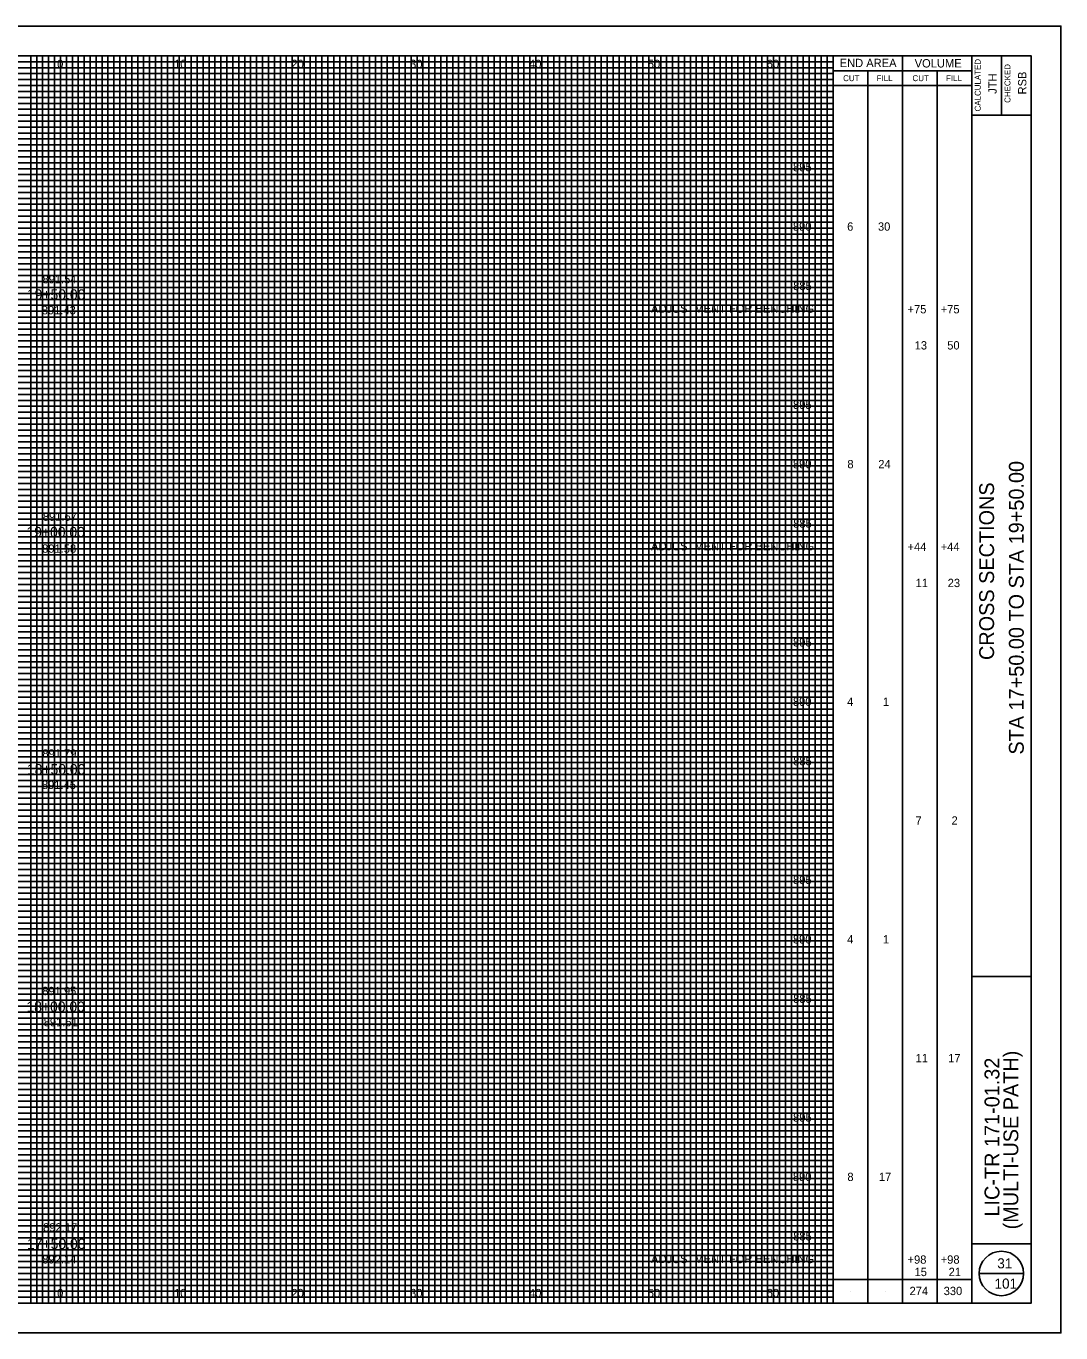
# Model space of a CAD drawing. Extents: x -10 to 160, y -2 to 2522.
# Drawn here: x 72.9 to 160, y 342.5 to 452.5 of the extents above; entities that cross this region are included whole.
import ezdxf

# ---------------------------------------------------------------- set-up
doc = ezdxf.new("R2010")
doc.units = 0
for name, color, linetype in [('GK_Cells', 7, 'Continuous'), ('GK_Patterns', 7, 'Continuous'), ('TX_P_10', 7, 'Continuous'), ('TX_X_10', 7, 'Continuous'), ('XS_P_Finished_Grade_Seeded', 7, 'Continuous'), ('XS_P_Pavt_Surface', 7, 'Continuous'), ('XS_P_Subgrade', 7, 'Continuous'), ('XS_X_Ground_Line', 7, 'Continuous')]:
    doc.layers.add(name, color=color, linetype=linetype)

msp = doc.modelspace()

# ---------------------------------------------------------------- linework, layer by layer
at = {"layer": 'GK_Cells'}
msp.add_lwpolyline([(-10, 342.5), (160, 342.5), (160, 452.5), (-10, 452.5)], close=True, dxfattribs=at)
at = {"layer": 'TX_P_10'}
for p, q in [((140.83, 345), (140.83, 450)), ((146.67, 345), (146.67, 450)), ((140.83, 448.75), (152.5, 448.75)), ((143.75, 345), (143.75, 448.75)), ((149.58, 345), (149.58, 448.75)), ((140.83, 447.5), (152.5, 447.5)), ((140.83, 347), (152.5, 347)), ((153.12, 347.5), (156.88, 347.5)), ((142.29, 346), (142.29, 346)), ((145.21, 346), (145.21, 346)), ((148.12, 346), (148.12, 346)), ((151.04, 346), (151.04, 346))]:
    msp.add_line(p, q, dxfattribs=at)
msp.add_circle((155, 347.5), 1.87, dxfattribs=at)
at = {"layer": 'TX_X_10'}
for p, q in [((75.83, 345), (75.83, 450)), ((80.83, 345), (80.83, 450)), ((85.83, 345), (85.83, 450)), ((90.83, 345), (90.83, 450)), ((95.83, 345), (95.83, 450)), ((100.83, 345), (100.83, 450)), ((105.83, 345), (105.83, 450)), ((110.83, 345), (110.83, 450)), ((115.83, 345), (115.83, 450)), ((120.83, 345), (120.83, 450)), ((125.83, 345), (125.83, 450)), ((130.83, 345), (130.83, 450)), ((135.83, 345), (135.83, 450)), ((5.83, 445), (140.83, 445)), ((5.83, 440), (140.83, 440)), ((5.83, 435), (140.83, 435)), ((5.83, 430), (140.83, 430)), ((5.83, 425), (140.83, 425)), ((5.83, 420), (140.83, 420)), ((5.83, 415), (140.83, 415)), ((5.83, 410), (140.83, 410)), ((5.83, 405), (140.83, 405)), ((5.83, 400), (140.83, 400)), ((5.83, 395), (140.83, 395)), ((5.83, 390), (140.83, 390)), ((5.83, 385), (140.83, 385)), ((5.83, 380), (140.83, 380)), ((5.83, 375), (140.83, 375)), ((5.83, 370), (140.83, 370)), ((5.83, 365), (140.83, 365)), ((5.83, 360), (140.83, 360)), ((5.83, 355), (140.83, 355)), ((5.83, 350), (140.83, 350))]:
    msp.add_line(p, q, dxfattribs=at)
at = {"layer": 'XS_P_Pavt_Surface'}
for p, q in [((152.5, 345), (152.5, 450)), ((155, 450), (155, 445)), ((152.5, 445), (157.5, 445)), ((152.5, 372.5), (157.5, 372.5)), ((152.5, 350), (157.5, 350))]:
    msp.add_line(p, q, dxfattribs=at)
msp.add_lwpolyline([(0, 450), (157.5, 450), (157.5, 345), (0, 345)], close=True, dxfattribs=at)
at = {"layer": 'XS_X_Ground_Line'}
for p, q in [((73.33, 345), (73.33, 450)), ((73.83, 345), (73.83, 450)), ((74.33, 345), (74.33, 450)), ((74.83, 345), (74.83, 450)), ((75.33, 345), (75.33, 450)), ((76.33, 345), (76.33, 450)), ((76.83, 345), (76.83, 450)), ((77.33, 345), (77.33, 450)), ((77.83, 345), (77.83, 450)), ((78.33, 345), (78.33, 450)), ((78.83, 345), (78.83, 450)), ((79.33, 345), (79.33, 450)), ((79.83, 345), (79.83, 450)), ((80.33, 345), (80.33, 450)), ((81.33, 345), (81.33, 450)), ((81.83, 345), (81.83, 450)), ((82.33, 345), (82.33, 450)), ((82.83, 345), (82.83, 450)), ((83.33, 345), (83.33, 450)), ((83.83, 345), (83.83, 450)), ((84.33, 345), (84.33, 450)), ((84.83, 345), (84.83, 450)), ((85.33, 345), (85.33, 450)), ((86.33, 345), (86.33, 450)), ((86.83, 345), (86.83, 450)), ((87.33, 345), (87.33, 450)), ((87.83, 345), (87.83, 450)), ((88.33, 345), (88.33, 450)), ((88.83, 345), (88.83, 450)), ((89.33, 345), (89.33, 450)), ((89.83, 345), (89.83, 450)), ((90.33, 345), (90.33, 450)), ((91.33, 345), (91.33, 450)), ((91.83, 345), (91.83, 450)), ((92.33, 345), (92.33, 450)), ((92.83, 345), (92.83, 450)), ((93.33, 345), (93.33, 450)), ((93.83, 345), (93.83, 450)), ((94.33, 345), (94.33, 450)), ((94.83, 345), (94.83, 450)), ((95.33, 345), (95.33, 450)), ((96.33, 345), (96.33, 450)), ((96.83, 345), (96.83, 450)), ((97.33, 345), (97.33, 450)), ((97.83, 345), (97.83, 450)), ((98.33, 345), (98.33, 450)), ((98.83, 345), (98.83, 450)), ((99.33, 345), (99.33, 450)), ((99.83, 345), (99.83, 450)), ((100.33, 345), (100.33, 450)), ((101.33, 345), (101.33, 450)), ((101.83, 345), (101.83, 450)), ((102.33, 345), (102.33, 450)), ((102.83, 345), (102.83, 450)), ((103.33, 345), (103.33, 450)), ((103.83, 345), (103.83, 450)), ((104.33, 345), (104.33, 450)), ((104.83, 345), (104.83, 450)), ((105.33, 345), (105.33, 450)), ((106.33, 345), (106.33, 450)), ((106.83, 345), (106.83, 450)), ((107.33, 345), (107.33, 450)), ((107.83, 345), (107.83, 450)), ((108.33, 345), (108.33, 450)), ((108.83, 345), (108.83, 450)), ((109.33, 345), (109.33, 450)), ((109.83, 345), (109.83, 450)), ((110.33, 345), (110.33, 450)), ((111.33, 345), (111.33, 450)), ((111.83, 345), (111.83, 450)), ((112.33, 345), (112.33, 450)), ((112.83, 345), (112.83, 450)), ((113.33, 345), (113.33, 450)), ((113.83, 345), (113.83, 450)), ((114.33, 345), (114.33, 450)), ((114.83, 345), (114.83, 450)), ((115.33, 345), (115.33, 450)), ((116.33, 345), (116.33, 450)), ((116.83, 345), (116.83, 450)), ((117.33, 345), (117.33, 450)), ((117.83, 345), (117.83, 450)), ((118.33, 345), (118.33, 450)), ((118.83, 345), (118.83, 450)), ((119.33, 345), (119.33, 450)), ((119.83, 345), (119.83, 450)), ((120.33, 345), (120.33, 450)), ((121.33, 345), (121.33, 450)), ((121.83, 345), (121.83, 450)), ((122.33, 345), (122.33, 450)), ((122.83, 345), (122.83, 450)), ((123.33, 345), (123.33, 450)), ((123.83, 345), (123.83, 450)), ((124.33, 345), (124.33, 450)), ((124.83, 345), (124.83, 450)), ((125.33, 345), (125.33, 450)), ((126.33, 345), (126.33, 450)), ((126.83, 345), (126.83, 450)), ((127.33, 345), (127.33, 450)), ((127.83, 345), (127.83, 450)), ((128.33, 345), (128.33, 450)), ((128.83, 345), (128.83, 450)), ((129.33, 345), (129.33, 450)), ((129.83, 345), (129.83, 450)), ((130.33, 345), (130.33, 450)), ((131.33, 345), (131.33, 450)), ((131.83, 345), (131.83, 450)), ((132.33, 345), (132.33, 450)), ((132.83, 345), (132.83, 450)), ((133.33, 345), (133.33, 450)), ((133.83, 345), (133.83, 450)), ((134.33, 345), (134.33, 450)), ((134.83, 345), (134.83, 450)), ((135.33, 345), (135.33, 450)), ((136.33, 345), (136.33, 450)), ((136.83, 345), (136.83, 450)), ((137.33, 345), (137.33, 450)), ((137.83, 345), (137.83, 450)), ((138.33, 345), (138.33, 450)), ((138.83, 345), (138.83, 450)), ((139.33, 345), (139.33, 450)), ((139.83, 345), (139.83, 450)), ((140.33, 345), (140.33, 450)), ((5.83, 449.5), (140.83, 449.5)), ((5.83, 449), (140.83, 449)), ((5.83, 448.5), (140.83, 448.5)), ((5.83, 448), (140.83, 448)), ((5.83, 447.5), (140.83, 447.5)), ((5.83, 447), (140.83, 447)), ((5.83, 446.5), (140.83, 446.5)), ((5.83, 446), (140.83, 446)), ((5.83, 445.5), (140.83, 445.5)), ((5.83, 444.5), (140.83, 444.5)), ((5.83, 444), (140.83, 444)), ((5.83, 443.5), (140.83, 443.5)), ((5.83, 443), (140.83, 443)), ((5.83, 442.5), (140.83, 442.5)), ((5.83, 442), (140.83, 442)), ((5.83, 441.5), (140.83, 441.5)), ((5.83, 441), (140.83, 441)), ((5.83, 440.5), (140.83, 440.5)), ((5.83, 439.5), (140.83, 439.5)), ((5.83, 439), (140.83, 439)), ((5.83, 438.5), (140.83, 438.5)), ((5.83, 438), (140.83, 438)), ((5.83, 437.5), (140.83, 437.5)), ((5.83, 437), (140.83, 437)), ((5.83, 436.5), (140.83, 436.5)), ((5.83, 436), (140.83, 436)), ((5.83, 435.5), (140.83, 435.5)), ((5.83, 434.5), (140.83, 434.5)), ((5.83, 434), (140.83, 434)), ((5.83, 433.5), (140.83, 433.5)), ((5.83, 433), (140.83, 433)), ((5.83, 432.5), (140.83, 432.5)), ((5.83, 432), (140.83, 432)), ((5.83, 431.5), (140.83, 431.5)), ((5.83, 431), (140.83, 431)), ((5.83, 430.5), (140.83, 430.5)), ((5.83, 429.5), (140.83, 429.5)), ((5.83, 429), (140.83, 429)), ((5.83, 428.5), (140.83, 428.5)), ((5.83, 428), (140.83, 428)), ((5.83, 427.5), (140.83, 427.5)), ((5.83, 427), (140.83, 427)), ((5.83, 426.5), (140.83, 426.5)), ((5.83, 426), (140.83, 426)), ((5.83, 425.5), (140.83, 425.5)), ((5.83, 424.5), (140.83, 424.5)), ((5.83, 424), (140.83, 424)), ((5.83, 423.5), (140.83, 423.5)), ((5.83, 423), (140.83, 423)), ((5.83, 422.5), (140.83, 422.5)), ((5.83, 422), (140.83, 422)), ((5.83, 421.5), (140.83, 421.5)), ((5.83, 421), (140.83, 421)), ((5.83, 420.5), (140.83, 420.5)), ((5.83, 419.5), (140.83, 419.5)), ((5.83, 419), (140.83, 419)), ((5.83, 418.5), (140.83, 418.5)), ((5.83, 418), (140.83, 418)), ((5.83, 417.5), (140.83, 417.5)), ((5.83, 417), (140.83, 417)), ((5.83, 416.5), (140.83, 416.5)), ((5.83, 416), (140.83, 416)), ((5.83, 415.5), (140.83, 415.5)), ((5.83, 414.5), (140.83, 414.5)), ((5.83, 414), (140.83, 414)), ((5.83, 413.5), (140.83, 413.5)), ((5.83, 413), (140.83, 413)), ((5.83, 412.5), (140.83, 412.5)), ((5.83, 412), (140.83, 412)), ((5.83, 411.5), (140.83, 411.5)), ((5.83, 411), (140.83, 411)), ((5.83, 410.5), (140.83, 410.5)), ((5.83, 409.5), (140.83, 409.5)), ((5.83, 409), (140.83, 409)), ((5.83, 408.5), (140.83, 408.5)), ((5.83, 408), (140.83, 408)), ((5.83, 407.5), (140.83, 407.5)), ((5.83, 407), (140.83, 407)), ((5.83, 406.5), (140.83, 406.5)), ((5.83, 406), (140.83, 406)), ((5.83, 405.5), (140.83, 405.5)), ((5.83, 404.5), (140.83, 404.5)), ((5.83, 404), (140.83, 404)), ((5.83, 403.5), (140.83, 403.5)), ((5.83, 403), (140.83, 403)), ((5.83, 402.5), (140.83, 402.5)), ((5.83, 402), (140.83, 402)), ((5.83, 401.5), (140.83, 401.5)), ((5.83, 401), (140.83, 401)), ((5.83, 400.5), (140.83, 400.5)), ((5.83, 399.5), (140.83, 399.5)), ((5.83, 399), (140.83, 399)), ((5.83, 398.5), (140.83, 398.5)), ((5.83, 398), (140.83, 398)), ((5.83, 397.5), (140.83, 397.5)), ((5.83, 397), (140.83, 397)), ((5.83, 396.5), (140.83, 396.5)), ((5.83, 396), (140.83, 396)), ((5.83, 395.5), (140.83, 395.5)), ((5.83, 394.5), (140.83, 394.5)), ((5.83, 394), (140.83, 394)), ((5.83, 393.5), (140.83, 393.5)), ((5.83, 393), (140.83, 393)), ((5.83, 392.5), (140.83, 392.5)), ((5.83, 392), (140.83, 392)), ((5.83, 391.5), (140.83, 391.5)), ((5.83, 391), (140.83, 391)), ((5.83, 390.5), (140.83, 390.5)), ((5.83, 389.5), (140.83, 389.5)), ((5.83, 389), (140.83, 389)), ((5.83, 388.5), (140.83, 388.5)), ((5.83, 388), (140.83, 388)), ((5.83, 387.5), (140.83, 387.5)), ((5.83, 387), (140.83, 387)), ((5.83, 386.5), (140.83, 386.5)), ((5.83, 386), (140.83, 386)), ((5.83, 385.5), (140.83, 385.5)), ((5.83, 384.5), (140.83, 384.5)), ((5.83, 384), (140.83, 384)), ((5.83, 383.5), (140.83, 383.5)), ((5.83, 383), (140.83, 383)), ((5.83, 382.5), (140.83, 382.5)), ((5.83, 382), (140.83, 382)), ((5.83, 381.5), (140.83, 381.5)), ((5.83, 381), (140.83, 381)), ((5.83, 380.5), (140.83, 380.5)), ((5.83, 379.5), (140.83, 379.5)), ((5.83, 379), (140.83, 379)), ((5.83, 378.5), (140.83, 378.5)), ((5.83, 378), (140.83, 378)), ((5.83, 377.5), (140.83, 377.5)), ((5.83, 377), (140.83, 377)), ((5.83, 376.5), (140.83, 376.5)), ((5.83, 376), (140.83, 376)), ((5.83, 375.5), (140.83, 375.5)), ((5.83, 374.5), (140.83, 374.5)), ((5.83, 374), (140.83, 374)), ((5.83, 373.5), (140.83, 373.5)), ((5.83, 373), (140.83, 373)), ((5.83, 372.5), (140.83, 372.5)), ((5.83, 372), (140.83, 372)), ((5.83, 371.5), (140.83, 371.5)), ((5.83, 371), (140.83, 371)), ((5.83, 370.5), (140.83, 370.5)), ((5.83, 369.5), (140.83, 369.5)), ((5.83, 369), (140.83, 369)), ((5.83, 368.5), (140.83, 368.5)), ((5.83, 368), (140.83, 368)), ((5.83, 367.5), (140.83, 367.5)), ((5.83, 367), (140.83, 367)), ((5.83, 366.5), (140.83, 366.5)), ((5.83, 366), (140.83, 366)), ((5.83, 365.5), (140.83, 365.5)), ((5.83, 364.5), (140.83, 364.5)), ((5.83, 364), (140.83, 364)), ((5.83, 363.5), (140.83, 363.5)), ((5.83, 363), (140.83, 363)), ((5.83, 362.5), (140.83, 362.5)), ((5.83, 362), (140.83, 362)), ((5.83, 361.5), (140.83, 361.5)), ((5.83, 361), (140.83, 361)), ((5.83, 360.5), (140.83, 360.5)), ((5.83, 359.5), (140.83, 359.5)), ((5.83, 359), (140.83, 359)), ((5.83, 358.5), (140.83, 358.5)), ((5.83, 358), (140.83, 358)), ((5.83, 357.5), (140.83, 357.5)), ((5.83, 357), (140.83, 357)), ((5.83, 356.5), (140.83, 356.5)), ((5.83, 356), (140.83, 356)), ((5.83, 355.5), (140.83, 355.5)), ((5.83, 354.5), (140.83, 354.5)), ((5.83, 354), (140.83, 354)), ((5.83, 353.5), (140.83, 353.5)), ((5.83, 353), (140.83, 353)), ((5.83, 352.5), (140.83, 352.5)), ((5.83, 352), (140.83, 352)), ((5.83, 351.5), (140.83, 351.5)), ((5.83, 351), (140.83, 351)), ((5.83, 350.5), (140.83, 350.5)), ((5.83, 349.5), (140.83, 349.5)), ((5.83, 349), (140.83, 349)), ((5.83, 348.5), (140.83, 348.5)), ((5.83, 348), (140.83, 348)), ((5.83, 347.5), (140.83, 347.5)), ((5.83, 347), (140.83, 347)), ((5.83, 346.5), (140.83, 346.5)), ((5.83, 346), (140.83, 346)), ((5.83, 345.5), (140.83, 345.5))]:
    msp.add_line(p, q, dxfattribs=at)

# ---------------------------------------------------------------- texts
at = {"layer": 'GK_Patterns'}
for s, height, p in [('0', 0.7, (75.55, 448.97)), ('0', 0.7, (75.55, 448.97)), ('10', 0.7, (85.39, 448.97)), ('20', 0.7, (95.26, 448.97)), ('30', 0.7, (105.25, 448.97)), ('40', 0.7, (115.25, 448.97)), ('50', 0.7, (125.25, 448.97)), ('60', 0.7, (135.25, 448.97)), ('895', 0.7, (137.47, 440.28)), ('890', 0.7, (137.46, 435.28)), ('6', 0.7, (142.02, 435.28)), ('30', 0.7, (144.61, 435.28)), ('19+50.00', 0.875, (73.01, 429.47)), ('885', 0.7, (137.48, 430.28)), ('ADJUSTMENT FOR BENCHING', 0.7, (125.52, 428.37)), ('+75', 0.7, (147.1, 428.32)), ('+75', 0.7, (149.89, 428.32)), ('13', 0.7, (147.7, 425.28)), ('50', 0.7, (150.44, 425.28)), ('895', 0.7, (137.47, 420.28)), ('890', 0.7, (137.46, 415.28)), ('8', 0.7, (142.04, 415.28)), ('24', 0.7, (144.64, 415.28)), ('19+00.00', 0.875, (72.97, 409.47)), ('885', 0.7, (137.48, 410.28)), ('ADJUSTMENT FOR BENCHING', 0.7, (125.52, 408.37)), ('+44', 0.7, (147.1, 408.32)), ('+44', 0.7, (149.89, 408.32)), ('11', 0.7, (147.78, 405.28)), ('23', 0.7, (150.48, 405.28)), ('895', 0.7, (137.47, 400.28)), ('890', 0.7, (137.46, 395.28)), ('4', 0.7, (142.02, 395.28)), ('1', 0.7, (145.03, 395.28)), ('885', 0.7, (137.48, 390.28)), ('18+50.00', 0.875, (73.01, 389.5)), ('7', 0.7, (147.77, 385.28)), ('2', 0.7, (150.8, 385.28)), ('895', 0.7, (137.47, 380.28)), ('890', 0.7, (137.46, 375.28)), ('4', 0.7, (142.02, 375.28)), ('1', 0.7, (145.03, 375.28)), ('885', 0.7, (137.48, 370.28)), ('18+00.00', 0.875, (72.97, 369.52)), ('11', 0.7, (147.78, 365.28)), ('17', 0.7, (150.52, 365.28)), ('895', 0.7, (137.47, 360.28)), ('890', 0.7, (137.46, 355.28)), ('8', 0.7, (142.04, 355.28)), ('17', 0.7, (144.69, 355.28)), ('885', 0.7, (137.48, 350.28)), ('17+50.00', 0.875, (73.02, 349.56)), ('ADJUSTMENT FOR BENCHING', 0.7, (125.52, 348.37)), ('+98', 0.7, (147.1, 348.32)), ('+98', 0.7, (149.89, 348.32)), ('15', 0.7, (147.69, 347.28)), ('21', 0.7, (150.56, 347.28)), ('0', 0.7, (75.55, 345.5)), ('0', 0.7, (75.55, 345.5)), ('10', 0.7, (85.39, 345.5)), ('20', 0.7, (95.26, 345.5)), ('30', 0.7, (105.25, 345.5)), ('40', 0.7, (115.25, 345.5)), ('50', 0.7, (125.25, 345.5)), ('60', 0.7, (135.25, 345.5)), ('274', 0.7, (147.27, 345.68)), ('330', 0.7, (150.14, 345.68))]:
    msp.add_text(s, height=height, dxfattribs=at).set_placement(p)
at = {"layer": 'TX_P_10'}
for s, height, p in [('END AREA', 0.7, (141.39, 449.05)), ('VOLUME', 0.7, (147.7, 449.02)), ('CUT', 0.5, (141.68, 447.87)), ('FILL', 0.5, (144.5, 447.87)), ('CUT', 0.5, (147.52, 447.87)), ('FILL', 0.5, (150.34, 447.87)), ('31', 0.85, (154.65, 347.93)), ('101', 0.85, (154.42, 346.22))]:
    msp.add_text(s, height=height, dxfattribs=at).set_placement(p)
for s, height, p in [('CALCULATED', 0.5, (153.26, 445.32)), ('CHECKED', 0.5, (155.76, 446.04)), ('JTH', 0.7, (154.6, 446.8)), ('RSB', 0.7, (157.1, 446.75)), ('STA 17+50.00 TO STA 19+50.00', 1.25, (156.88, 391.18)), ('CROSS SECTIONS', 1.25, (154.38, 399.14)), ('LIC-TR 171-01.32', 1.25, (154.83, 352.29)), ('(MULTI-USE PATH)', 1.25, (156.42, 351.21))]:
    msp.add_text(s, height=height, rotation=90, dxfattribs=at).set_placement(p)
at = {"layer": 'XS_P_Finished_Grade_Seeded'}
for s, p in [('891.43', (74.26, 428.24)), ('891.58', (74.29, 408.17)), ('891.45', (74.27, 388.28)), ('891.61', (74.42, 368.31)), ('892.14', (74.3, 348.34))]:
    msp.add_text(s, height=0.7, dxfattribs=at).set_placement(p)
at = {"layer": 'XS_P_Subgrade'}
for s, p in [('891.54', (74.32, 430.85)), ('891.67', (74.35, 410.86)), ('891.79', (74.31, 390.92)), ('891.95', (74.3, 370.93)), ('892.17', (74.37, 351.03))]:
    msp.add_text(s, height=0.7, dxfattribs=at).set_placement(p)

doc.saveas('drawing.dxf')
